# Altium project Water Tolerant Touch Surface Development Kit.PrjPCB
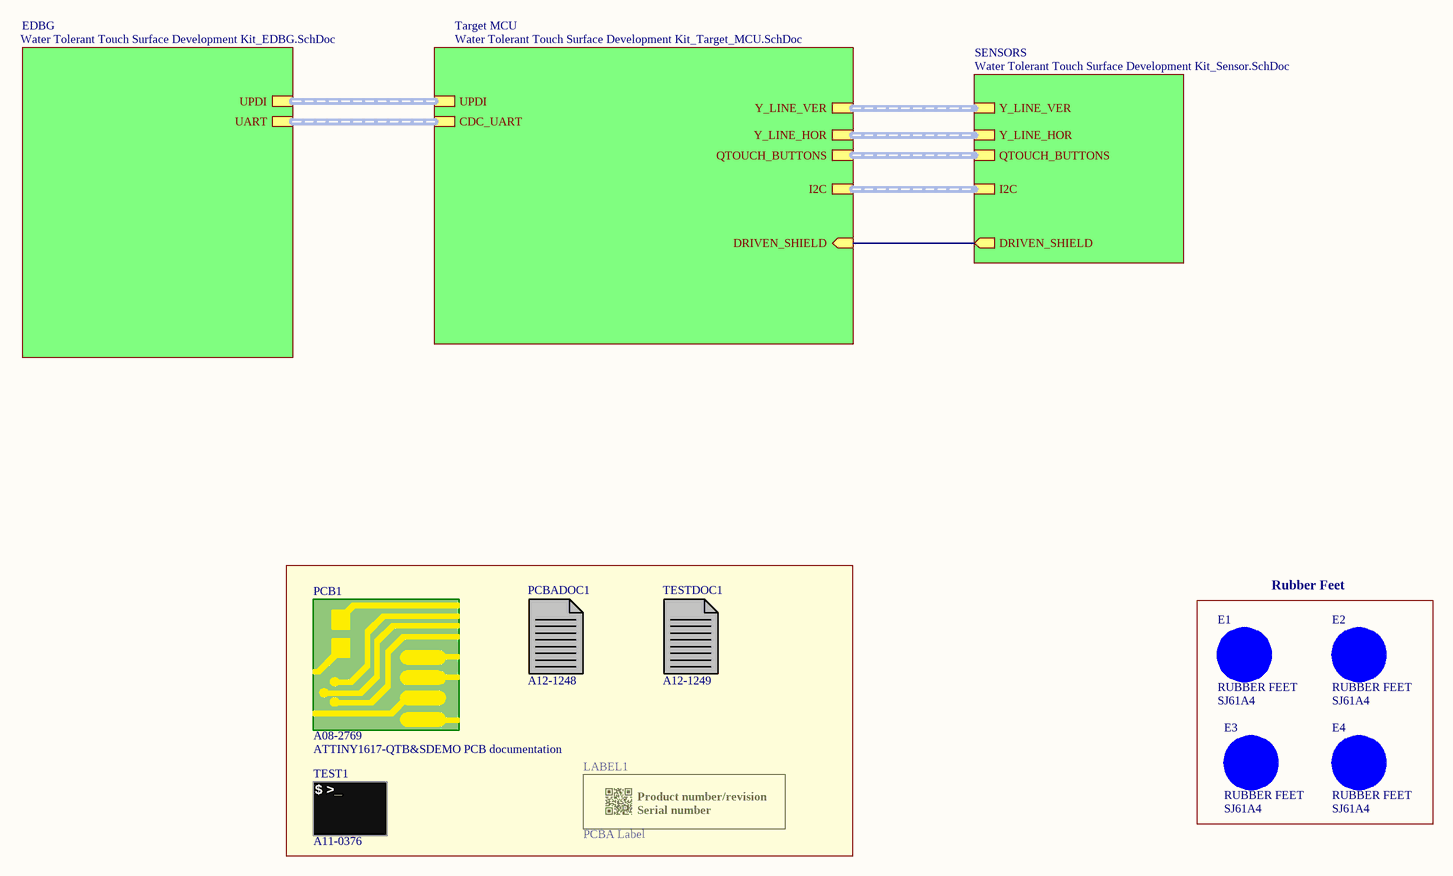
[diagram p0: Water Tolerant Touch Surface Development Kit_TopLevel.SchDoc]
4 sheets, 95 parts. Net scope: hierarchical (ports join the sheet entries above them; power ports are global).
Board file: Water Tolerant Touch Surface Development Kit.PcbDoc
Sheets:
  Water Tolerant Touch Surface Development Kit_TopLevel.SchDoc
    EDBG = Water Tolerant Touch Surface Development Kit_EDBG.SchDoc
    SENSORS = Water Tolerant Touch Surface Development Kit_Sensor.SchDoc
    Target MCU = Water Tolerant Touch Surface Development Kit_Target_MCU.SchDoc

## Sheet Water Tolerant Touch Surface Development Kit_TopLevel.SchDoc: Water Tolerant Touch Surface Development Kit
size A3; Author: Nitinkumar; CompanyName: Microchip; Engineer: Sivaram.SL; Organization: Microchip India; Address1: Sholinganallur; Address2: Chennai; Address3: INDIA; DocumentNumber: A09-3028; Revision: 3; SheetNumber: 1; SheetTotal: 4; PageSetup: Record=PageOptions¦CenterHorizontal=True¦CenterVertical=True¦PrintScale=1.01¦XCorrection=1.00¦YCorrection=1.00¦PrintKind=1¦BorderSize=5000000¦LeftOffset=0¦BottomOffset=0¦Orientation=2¦PaperLength=1000¦PaperWidth=1000¦Scale=100¦PaperSource=7¦PrintQuality=-4¦MediaType=1¦DitherType=10¦PaperKind=A3 (297 x 420 mm)¦PrintScaleMode=1; PCBNumber: A08-2769; PCBRevision: 3

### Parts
E1  RUBBER FEET  value SJ61A4  [AP8-01069]
E2  RUBBER FEET  value SJ61A4  [AP8-01069]
E3  RUBBER FEET  value SJ61A4  [AP8-01069]
E4  RUBBER FEET  value SJ61A4  [AP8-01069]
LABEL1  value PCBA Label  [AP8-00317]  (hidden comment: PCBA_LABEL)
PCB1  value ATTINY1617-QTB&SDEMO PCB documentation  AN: A08-2769  (hidden comment: PCB)  (mechanical)
PCBADOC1  AN: A12-1248  (hidden comment: PCBADOC)  (mechanical)
TEST1  AN: A11-0376  (hidden comment: TEST)  (mechanical)
TESTDOC1  AN: A12-1249  (hidden comment: TESTDOC)  (mechanical)

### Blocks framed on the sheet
Rubber Feet: E1-E4

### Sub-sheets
EDBG = Water Tolerant Touch Surface Development Kit_EDBG.SchDoc: UPDI (harness UPDI), UART (harness UART)
SENSORS = Water Tolerant Touch Surface Development Kit_Sensor.SchDoc: Y_LINE_VER (harness Y_LINE_VER), Y_LINE_HOR (harness Y_LINE_HOR), I2C (harness I2C), DRIVEN_SHIELD (out), QTOUCH_BUTTONS (harness QTOUCH_BUTTONS)
Target MCU = Water Tolerant Touch Surface Development Kit_Target_MCU.SchDoc: UPDI (harness UPDI), CDC_UART (harness CDC_UART), Y_LINE_VER (harness Y_LINE_HOR), Y_LINE_HOR (harness X LINES), I2C (harness I2C), DRIVEN_SHIELD (in), QTOUCH_BUTTONS (harness QTOUCH_BUTTONS)

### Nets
DRIVEN_SHIELD: sheet SENSORS/DRIVEN_SHIELD, sheet Target MCU/DRIVEN_SHIELD

Not connected (* = marked no-connect by the designer): E1 1(FIDUCIAL); E2 1(FIDUCIAL); E3 1(FIDUCIAL); E4 1(FIDUCIAL)

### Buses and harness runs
harness sheet EDBG/UART = sheet Target MCU/CDC_UART
harness sheet EDBG/UPDI = sheet Target MCU/UPDI
harness sheet SENSORS/I2C = sheet Target MCU/I2C
harness sheet SENSORS/QTOUCH_BUTTONS = sheet Target MCU/QTOUCH_BUTTONS
harness sheet SENSORS/Y_LINE_HOR = sheet Target MCU/Y_LINE_HOR
harness sheet SENSORS/Y_LINE_VER = sheet Target MCU/Y_LINE_VER

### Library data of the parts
E1-E4 = A08-2771: 7.9mm adhesive feet diam 9.5mm
LABEL1 = A09-0611: PCBA identification label PP Top White Gloss; PartGroup: Mechanical devices,Packaging materials,Printed Labels; Manufacturer: ACT Logimark AS; MPN: 505462; ComponentStatus: 'Active (verified)'
PCB1 = A08-2769: ATTINY1617-QTB&SDEMO PCB documentation
PCBADOC1 = A12-1248: ATTINY1617-QTB&SDEMO PCBA documentation
TEST1 = A11-0376: ATTINY1617-QTB&SDEMO Test Software
TESTDOC1 = A12-1249: ATTINY1617-QTB&SDEMO Test Instructions

## Sheet Water Tolerant Touch Surface Development Kit_EDBG.SchDoc: Water Tolerant Touch Surface Development Kit
size A3; Organization: Microchip India; Address1: Sholinganallur; Address2: Chennai; Address3: India; DocumentNumber: A09-3028; Revision: 3; SheetNumber: 3; SheetTotal: 4; PageSetup: Record=PageOptions¦CenterHorizontal=True¦CenterVertical=True¦PrintScale=1.01¦XCorrection=1.00¦YCorrection=1.00¦PrintKind=1¦BorderSize=5000000¦LeftOffset=0¦BottomOffset=0¦Orientation=2¦PaperLength=1000¦PaperWidth=1000¦Scale=100¦PaperSource=7¦PrintQuality=-4¦MediaType=1¦DitherType=10¦PaperKind=A3 (297 x 420 mm)¦PrintScaleMode=1; PCBNumber: A09-2769; PCBRevision: 3
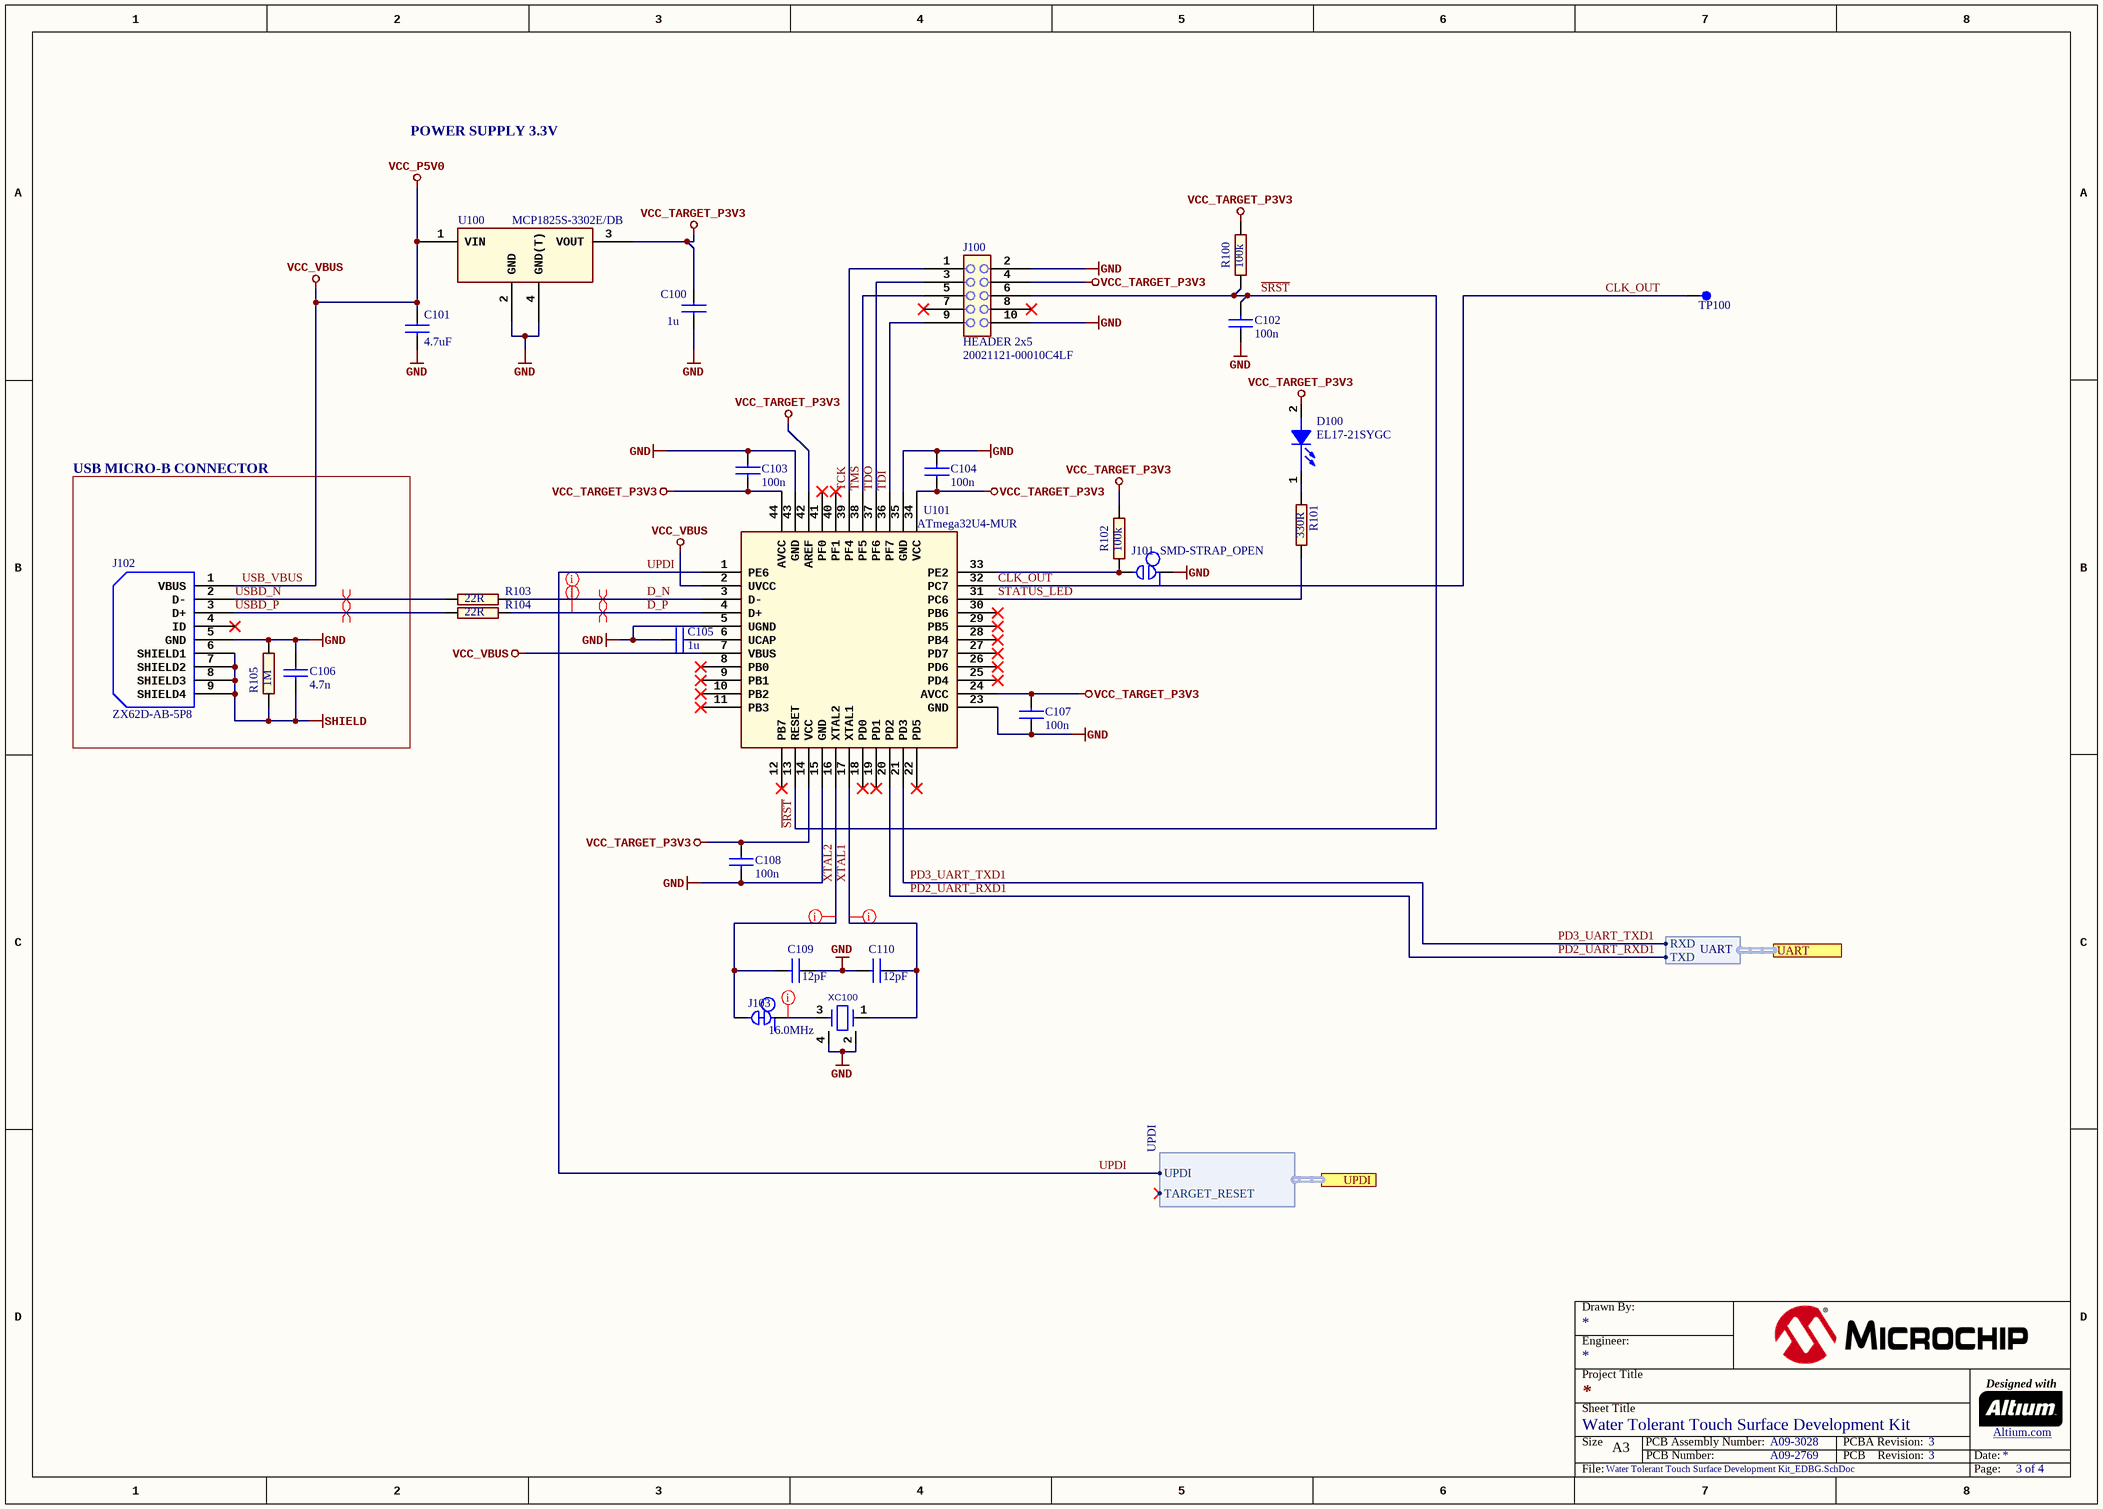
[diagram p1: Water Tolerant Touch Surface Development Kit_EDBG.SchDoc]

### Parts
C100  value 1u  [AP1-00001]
C101  value 4.7uF  [AP1-00039]  (hidden comment: CAP-NONPOL)
C102  value 100n  [AP1-00001]
C103  value 100n  [AP1-00001]
C104  value 100n  [AP1-00001]
C105  value 1u  [AP1-00001]
C106  value 4.7n  [AP1-00001]
C107  value 100n  [AP1-00001]
C108  value 100n  [AP1-00001]
C109  value 12pF  [AP1-00038]
C110  value 12pF  [AP1-00038]
D100  value EL17-21SYGC  [AP4-00013]
J100  HEADER 2x5  value 20021121-00010C4LF  [AP8-00109]
J101  value SMD-STRAP_OPEN  [AP9-00034]  (no BOM)
J102  value ZX62D-AB-5P8  [AP8-00852]  (hidden comment: 2,000 pieces per reel)
J103  (no value)  [AP9-00044]  (net tie, no BOM)
R100  value 100k  [AP2-00000]
R101  value 330R  [AP2-00000]  (hidden comment: R2)
R102  value 100k  [AP2-00000]
R103  value 22R  [AP2-00000]
R104  value 22R  [AP2-00000]
R105  value 1M  [AP2-00000]
TP100  (no value)  [AP8-00010]  (no BOM)
U100  value MCP1825S-3302E/DB  (hidden comment: MCP1825S-3302E_DB)
U101  value ATmega32U4-MUR  [AP6-00375]
XC100  value 16.0MHz  [AP7-00061]

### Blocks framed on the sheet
USB MICRO-B CONNECTOR: C106 J102 R105

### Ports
UART (harness UART), UPDI (harness UPDI)

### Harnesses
UART: RXD, TXD
UPDI: UPDI, TARGET_RESET

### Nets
GND: C100.2 C101.2 C102.1 C103.1 C104.2 C105.1 C106.1 C107.1 C108.2 C109.1 C110.2 J100.2 J100.10 J101.1 J102.5(GND) R105.2 U100.2(GND) U100.4(GND(T)) U101.5(UGND) U101.15(GND) U101.23(GND) U101.35(GND) U101.43(GND) U101.45(GND) XC100.2(GND) XC100.4(GND)
SHIELD: C106.2 J102.6(SHIELD1) J102.7(SHIELD2) J102.8(SHIELD3) J102.9(SHIELD4) R105.1
USB_VBUS: C101.1 J102.1(VBUS) U100.1(VIN) U101.2(UVCC) U101.7(VBUS)  [also labelled VCC_P5V0, VCC_VBUS]
VCC_TARGET_P3V3: C100.1 C103.2 C104.1 C107.2 C108.1 D100.2(ANODE) J100.4 R100.2 R102.2 U100.3(VOUT) U101.14(VCC) U101.24(AVCC) U101.34(VCC) U101.42(AREF) U101.44(AVCC)
CLK_OUT: TP100.1 U101.32(PC7)
D_N: R103.2 U101.3(D-)
D_P: R104.2 U101.4(D+)
PD2_UART_RXD1: U101.20(PD2) ; port UART.TXD  [project net PB2_UART_TX]
PD3_UART_TXD1: U101.21(PD3) ; port UART.RXD  [project net PB3_UART_RX]
~{SRST}: C102.2 J100.6 R100.1 U101.13(RESET)
STATUS_LED: R101.1 U101.31(PC6)
TCK: J100.1 U101.39(PF4)
TDI: J100.9 U101.36(PF7)
TDO: J100.3 U101.37(PF6)
TMS: J100.5 U101.38(PF5)
UPDI: U101.1(PE6) ; port UPDI.UPDI  [project net PA0_UPDI_RST]
USBD_N: J102.2(D-) R103.1
USBD_P: J102.3(D+) R104.1
XTAL1: C110.1 U101.17(XTAL1) XC100.1(IN)
XTAL2: C109.2 J103.2 U101.16(XTAL2)
NetC105_2: C105.2 U101.6(UCAP)
NetD100_1: D100.1(CATHODE) R101.2
NetJ101_2: J101.2 R102.1 U101.33(PE2)
NetJ103_1: J103.1 XC100.3(OUT)

Not connected (* = marked no-connect by the designer): J100 7* 8*; J102 4(ID)*; U101 8(PB0)* 9(PB1)* 10(PB2)* 11(PB3)* 12(PB7)* 18(PD0)* 19(PD1)* 22(PD5)* 25(PD4)* 26(PD6)* 27(PD7)* 28(PB4)* 29(PB5)* 30(PB6)* 40(PF1)* 41(PF0)*

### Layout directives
differential pair: D_N, D_P, USBD_N, USBD_P
rule Assembly Testpoint Usage [Testpoint - Not Allowed    Multiple - Not Allowed]: D_N, D_P, NetJ103_1, XTAL1, XTAL2

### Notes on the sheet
- POWER SUPPLY 3.3V

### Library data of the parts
C100 C105 = A01-0286: Ceramic capacitor, SMD 0402, X5R, 6.3V, +/-10% (de26942); PartGroup: Capacitors,Ceramic,SMD 0402; Manufacturer: Kemet; MPN: C0402C105K9PAC; TemperatureRange: -55 to 85 deg C; ComponentStatus: 'Active (verified)'
C101 = A01-0377: Ceramic capacitor, SMD 0603, X5R, 10V, 10% (de31036); PartGroup: Capacitors,Ceramic,SMD 0603; Manufacturer: WALSIN Technology Corporation; MPN: 0603X475K100CT; TemperatureRange: -55 - +85 deg C; ComponentStatus: 'Active (verified)'
C102-C104 C107 C108 = A01-0246: Ceramic capacitor, SMD 0402, X7R, 16V, +/-10%; PartGroup: Capacitors,Ceramic,SMD 0402; Manufacturer: Kemet; MPN: C0402C104K4RACTU; TemperatureRange: -55 - +125 deg C; ComponentStatus: 'Active (verified)'
C106 = A01-0046: Ceramic capacitor, SMD 0402, X7R, 25V, +/-10% (de35287); PartGroup: Capacitors,Ceramic,SMD 0402; TemperatureRange: -55 - +125 deg C; ComponentStatus: 'Active (verified)'
C109 C110 = A01-0355: Ceramic capacitor, SMD 0402, NP0, 50V, +/-5% (de19819); PartGroup: Capacitors,Ceramic,SMD 0402; Manufacturer: Kyocera-elco; MPN: CM05CG120J50AH; Tolerance: 5%; TemperatureRange: -55 - +125 deg C; ComponentStatus: 'Active (verified)'
D100 = A10-0018: LED, Green, Wave length=575nm, SMD 0805, ±70°; PartGroup: Opto,LEDs,SMD; Manufacturer: Everlight; TemperatureRange: -40 - +85 deg C; ComponentStatus: 'Active (verified)'
J100 = A08-0022: 2x5 pin header, 1.27mm pitch, SMD; PartGroup: Mechanical devices,Connectors,Pin headers; Manufacturer: HARWIN; MPN: M50-3600542; ComponentStatus: 'Active (verified)'
J101 = A09-0483: Default open SMD strap; PartGroup: Mechanical devices,PCB implemented components; ComponentStatus: 'Active (verified)'
J102 = A08-2112: Micro USB AB Connector, Standard SMT + DIP; PartGroup: Mechanical devices,Connectors,USB; Manufacturer: HIROSE; MPN: ZX62D-AB-5P8(30); ComponentStatus: 'Active (verified)'
J103 = A09-0783: Default closed SMD strap, 0603 size; PartGroup: Mechanical devices,PCB implemented components; Value: SMD-STRAP_0603_CLOSED; ComponentStatus: 'Active (verified)'
R100 R102 = A02-0260: Thick film resistor, SMD 0402, 1/16W, 1%; PartGroup: Resistors,SMD,0402 1%; Manufacturer: ASJ; MPN: CR10-1003-FK; TemperatureRange: -55ï¿½ to +125ï¿½C; ComponentStatus: 'Active (verified)'
R101 = A02-0200: Thick film resistor, SMD 0402, 1/16W, 1%; PartGroup: Resistors,SMD,0402 1%; TemperatureRange: -55 - +125 deg C; ComponentStatus: 'Active (verified)'
R103 R104 = A02-0172: Thick film resistor, SMD 0402, 1/16W, 1% (de23607); PartGroup: Resistors,SMD,0402 1%; Manufacturer: Samsung; MPN: RC100SF22R0CS; TemperatureRange: -55 - +125 deg C; ComponentStatus: 'Active (verified)'
R105 = A02-0284: Thick film resistor, SMD 0402, 1/16W, 1%; PartGroup: Resistors,SMD,0402 1%; Manufacturer: ASJ; MPN: CR10-1004-FK; TemperatureRange: -55 - +125 deg C; ComponentStatus: 'Active (verified)'
TP100 = A08-0004: Single SMD testpad; PartGroup: Mechanical devices,Connectors,Test points; ComponentStatus: 'Active (verified)'
U100 = A06-1533: LDO regulator, 3.3V fixed, 500mA, SOT-223
U101 = A06-0305: ATmega32U4 QFN package; PartGroup: Integrated Circuits,MCU, MPU, DSP,AVR MCU; Manufacturer: ATMEL; ComponentStatus: 'Active (verified)'
XC100 = A07-0078: 16MHz uXtal, 3.2 x 2.5 mm SMD, CL=9pF, 15PPM, ESR=80ohm(Max.; PartGroup: Frequency devices,Crystals,SMD; Manufacturer: Epson Toyocom; MPN: TSX-3225 16.0000MF09Z-AC3; TemperatureRange: -40Â°C to +85Â°C; ComponentStatus: 'Active (verified)'

## Sheet Water Tolerant Touch Surface Development Kit_Sensor.SchDoc: Water Tolerant Touch Surface Development Kit
size A3; Author: Nitinkumar; Organization: Microchip India; Address1: Sholinganallur; Address2: Chennai; Address3: India; DocumentNumber: A09-3028; Revision: 2; SheetNumber: 2; SheetTotal: 4; PageSetup: Record=PageOptions¦CenterHorizontal=True¦CenterVertical=True¦PrintScale=1.01¦XCorrection=1.00¦YCorrection=1.00¦PrintKind=1¦BorderSize=5000000¦LeftOffset=0¦BottomOffset=0¦Orientation=2¦PaperLength=1000¦PaperWidth=1000¦Scale=100¦PaperSource=7¦PrintQuality=-4¦MediaType=1¦DitherType=10¦PaperKind=A3 (297 x 420 mm)¦PrintScaleMode=1; PCBNumber: A09-2769; PCBRevision: 2
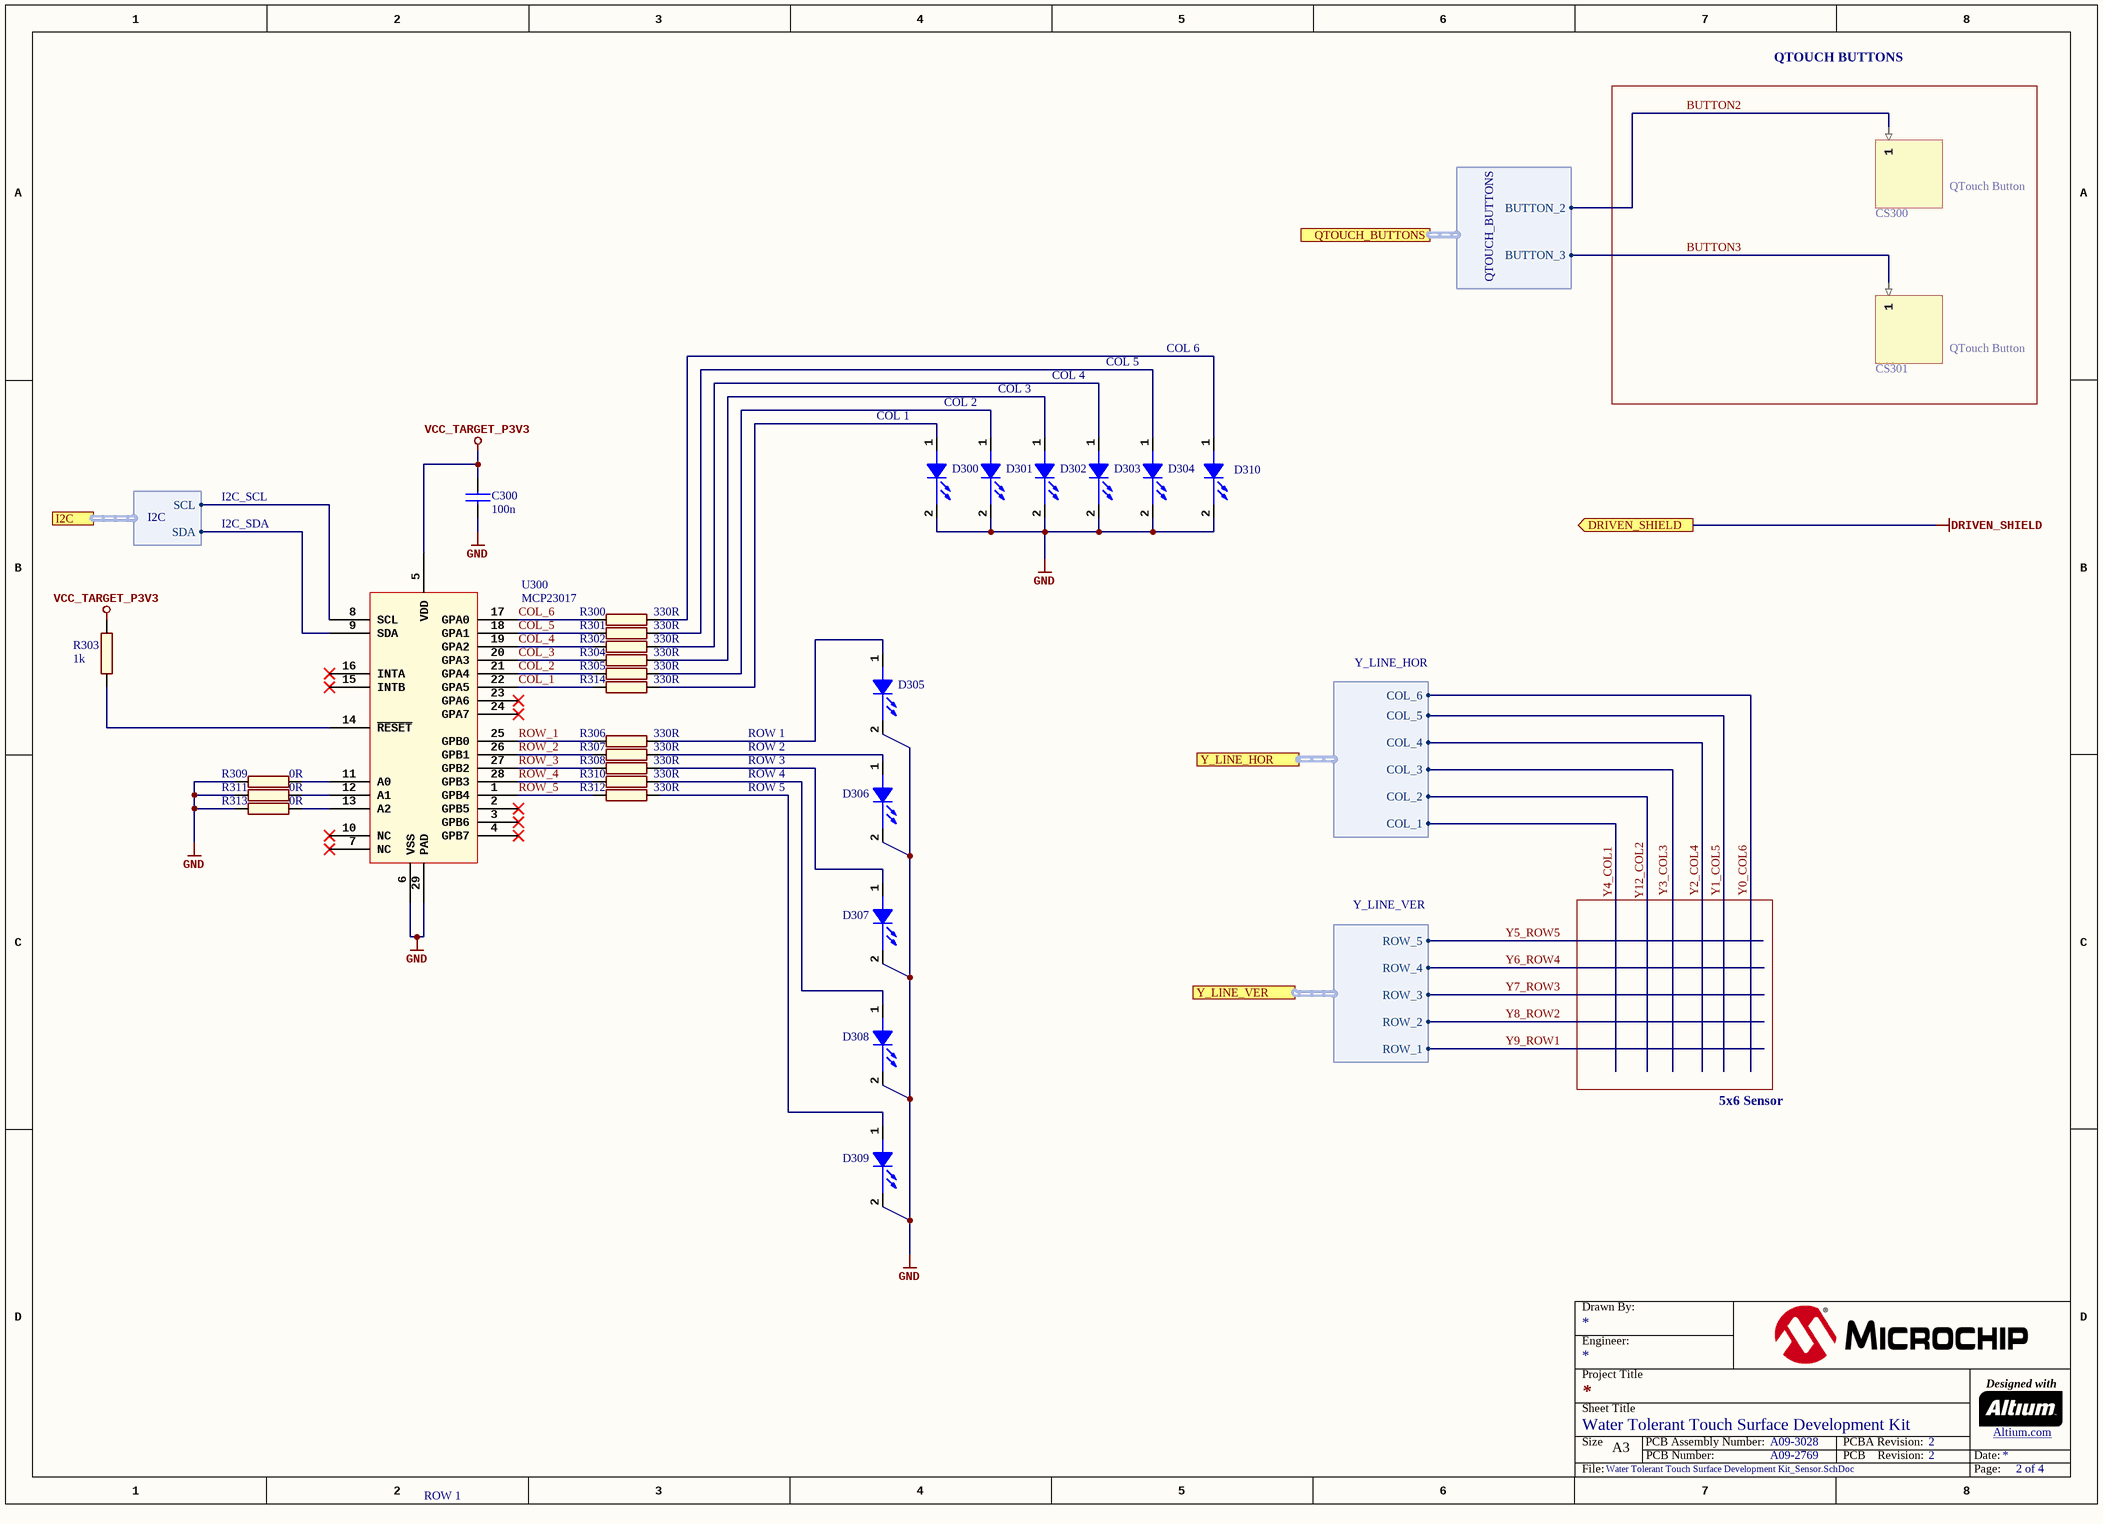
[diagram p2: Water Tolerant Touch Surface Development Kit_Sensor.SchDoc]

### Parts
C300  value 100n  [AP1-00053]
CS300  QTouch Button  (graphical)
CS301  QTouch Button  (graphical)
D300  LED_21  [AP4-00115]  (value not drawn)
D301  LED_21  [AP4-00115]  (value not drawn)
D302  LED_21  [AP4-00115]  (value not drawn)
D303  LED_21  [AP4-00115]  (value not drawn)
D304  LED_21  [AP4-00115]  (value not drawn)
D305  LED_21  [AP4-00115]  (value not drawn)
D306  LED_21  [AP4-00115]  (value not drawn)
D307  LED_21  [AP4-00115]  (value not drawn)
D308  LED_21  [AP4-00115]  (value not drawn)
D309  LED_21  [AP4-00115]  (value not drawn)
D310  LED_21  [AP4-00115]  (value not drawn)
R300  value 330R  [AP2-00000]  (hidden comment: R2)
R301  value 330R  [AP2-00000]  (hidden comment: R2)
R302  value 330R  [AP2-00000]  (hidden comment: R2)
R303  value 1k  [AP2-00011]
R304  value 330R  [AP2-00000]  (hidden comment: R2)
R305  value 330R  [AP2-00000]  (hidden comment: R2)
R306  value 330R  [AP2-00000]  (hidden comment: R2)
R307  value 330R  [AP2-00000]  (hidden comment: R2)
R308  value 330R  [AP2-00000]  (hidden comment: R2)
R309  value 0R  [AP2-00000]  (hidden comment: R2)
R310  value 330R  [AP2-00000]  (hidden comment: R2)
R311  value 0R  [AP2-00000]  (hidden comment: R2)
R312  value 330R  [AP2-00000]  (hidden comment: R2)
R313  value 0R  [AP2-00000]  (hidden comment: R2)
R314  value 330R  [AP2-00000]  (hidden comment: R2)
U300  value MCP23017  [AP6-00497]  (hidden comment: MCP23017-E_ML)

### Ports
DRIVEN_SHIELD (out), I2C (harness I2C), QTOUCH_BUTTONS (harness QTOUCH_BUTTONS), Y_LINE_HOR (harness Y_LINE_HOR), Y_LINE_VER (harness Y_LINE_VER)

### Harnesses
QTOUCH_BUTTONS: BUTTON_2, BUTTON_3
I2C: SDA, SCL
Y_LINE_VER: ROW_1, ROW_2, ROW_3, ROW_4, ROW_5
Y_LINE_HOR: COL_1, COL_2, COL_3, COL_4, COL_5, COL_6

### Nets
GND: C300.2 D300.2(CATHODE) D301.2(CATHODE) D302.2(CATHODE) D303.2(CATHODE) D304.2(CATHODE) D305.2(CATHODE) D306.2(CATHODE) D307.2(CATHODE) D308.2(CATHODE) D309.2(CATHODE) D310.2(CATHODE) R309.1 R311.1 R313.1 U300.6(VSS) U300.29(PAD)
VCC_TARGET_P3V3: C300.1 R303.2 U300.5(VDD)
BUTTON2: CS300.1 ; port QTOUCH_BUTTONS.BUTTON_2
BUTTON3: CS301.1 ; port QTOUCH_BUTTONS.BUTTON_3
COL_1: R314.1 U300.22(GPA5)
COL_2: R305.1 U300.21(GPA4)
COL_3: R304.1 U300.20(GPA3)
COL_4: R302.1 U300.19(GPA2)
COL_5: R301.1 U300.18(GPA1)
COL_6: R300.1 U300.17(GPA0)
PA1_I2C_SDA: U300.9(SDA) ; port I2C.SDA
PA2_I2C_SCL: U300.8(SCL) ; port I2C.SCL
ROW_1: R306.1 U300.25(GPB0)
ROW_2: R307.1 U300.26(GPB1)
ROW_3: R308.1 U300.27(GPB2)
ROW_4: R310.1 U300.28(GPB3)
ROW_5: R312.1 U300.1(GPB4)
NetD300_1: D300.1(ANODE) R314.2
NetD301_1: D301.1(ANODE) R305.2
NetD302_1: D302.1(ANODE) R304.2
NetD303_1: D303.1(ANODE) R302.2
NetD304_1: D304.1(ANODE) R301.2
NetD305_1: D305.1(ANODE) R306.2
NetD306_1: D306.1(ANODE) R307.2
NetD307_1: D307.1(ANODE) R308.2
NetD308_1: D308.1(ANODE) R310.2
NetD309_1: D309.1(ANODE) R312.2
NetD310_1: D310.1(ANODE) R300.2
NetR303_1: R303.1 U300.14(~{RESET})
NetR309_2: R309.2 U300.11(A0)
NetR311_2: R311.2 U300.12(A1)
NetR313_2: R313.2 U300.13(A2)

Not connected (* = marked no-connect by the designer): U300 2(GPB5)* 3(GPB6)* 4(GPB7)* 7(NC)* 10(NC)* 15(INTB)* 16(INTA)* 23(GPA6)* 24(GPA7)*

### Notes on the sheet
- QTOUCH BUTTONS
- COL 4
- COL 5
- COL 6
- (near D300) COL 1
- COL 2
- COL 3
- I2C_SCL
- I2C_SDA
- ROW 4
- ROW 3
- ROW 2
- ROW 1
- ROW 5
- 5x6 Sensor
- Labels drawn without touching a wire or pin: Y3_COL3

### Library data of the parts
C300 = A01-0246: as C102 on sheet Water Tolerant Touch Surface Development Kit_EDBG
CS300 CS301 = QTouchButton: ConfiguratorName: ATMEL_TOUCH; ConfigurationParameters: {}__sensorid[1]{}width[8]{}height[8]{}
D300-D310 = A10-0204: LED, SMD, RED, 3.2x1.2mm, reverse mount; Value: LTST-C250KRKT
R300-R302 R304-R308 R310 R312 R314 = A02-0200: Thick film resistor, SMD 0402, 1/16W, 1%; PartGroup: Resistors,SMD,0402 1%; Manufacturer: ASJ; MPN: CR10-3300-FK; TemperatureRange: -55 - +125 deg C; ComponentStatus: 'Active (verified)'
R303 = A02-0212: Thick film resistor, SMD 0402, 1/16W, 1%; PartGroup: Resistors,SMD,0402 1%; TemperatureRange: -55 - +125 deg C; ComponentStatus: 'Active (verified)'
R309 R311 R313 = A02-0163: RES 0.0 OHM 1/16W 0402 SMD; PartGroup: Resistors,SMD,0402 1%; Manufacturer: (n/a); MPN: RMCF0402ZT0R00; Tolerance: 1 %; TemperatureRange: -55 - +125 deg C; ComponentStatus: 'Active (verified)'
U300 = A06-1534: 16-Bit I/O Expander with I2C interface, 28-Lead QFN; PartGroup: Integrated Circuits,General linear; Manufacturer: Microchip Technology Inc; MPN: MCP23017-E/ML; TemperatureRange: -40Â°C to +125Â°C; ComponentStatus: 'Active (verified)'

## Sheet Water Tolerant Touch Surface Development Kit_Target_MCU.SchDoc: Water Tolerant Touch Surface Development Kit
size A3; Author: Nitinkumar; Engineer: Sivaram.SL; Organization: Microchip India; Address1: Sholinganallur; Address2: Chennai; Address3: India; DocumentNumber: A09-3028; Revision: 3; SheetNumber: 4; SheetTotal: 4; PageSetup: Record=PageOptions¦CenterHorizontal=True¦CenterVertical=True¦PrintScale=0.70¦XCorrection=1.00¦YCorrection=1.00¦PrintKind=1¦BorderSize=5000000¦LeftOffset=0¦BottomOffset=0¦Orientation=2¦PaperLength=1000¦PaperWidth=1000¦Scale=100¦PaperSource=7¦PrintQuality=-4¦MediaType=1¦DitherType=10¦PaperKind=A3 (297 x 420 mm)¦PrintScaleMode=1; PCBNumber: A09-2769; PCBRevision: 3
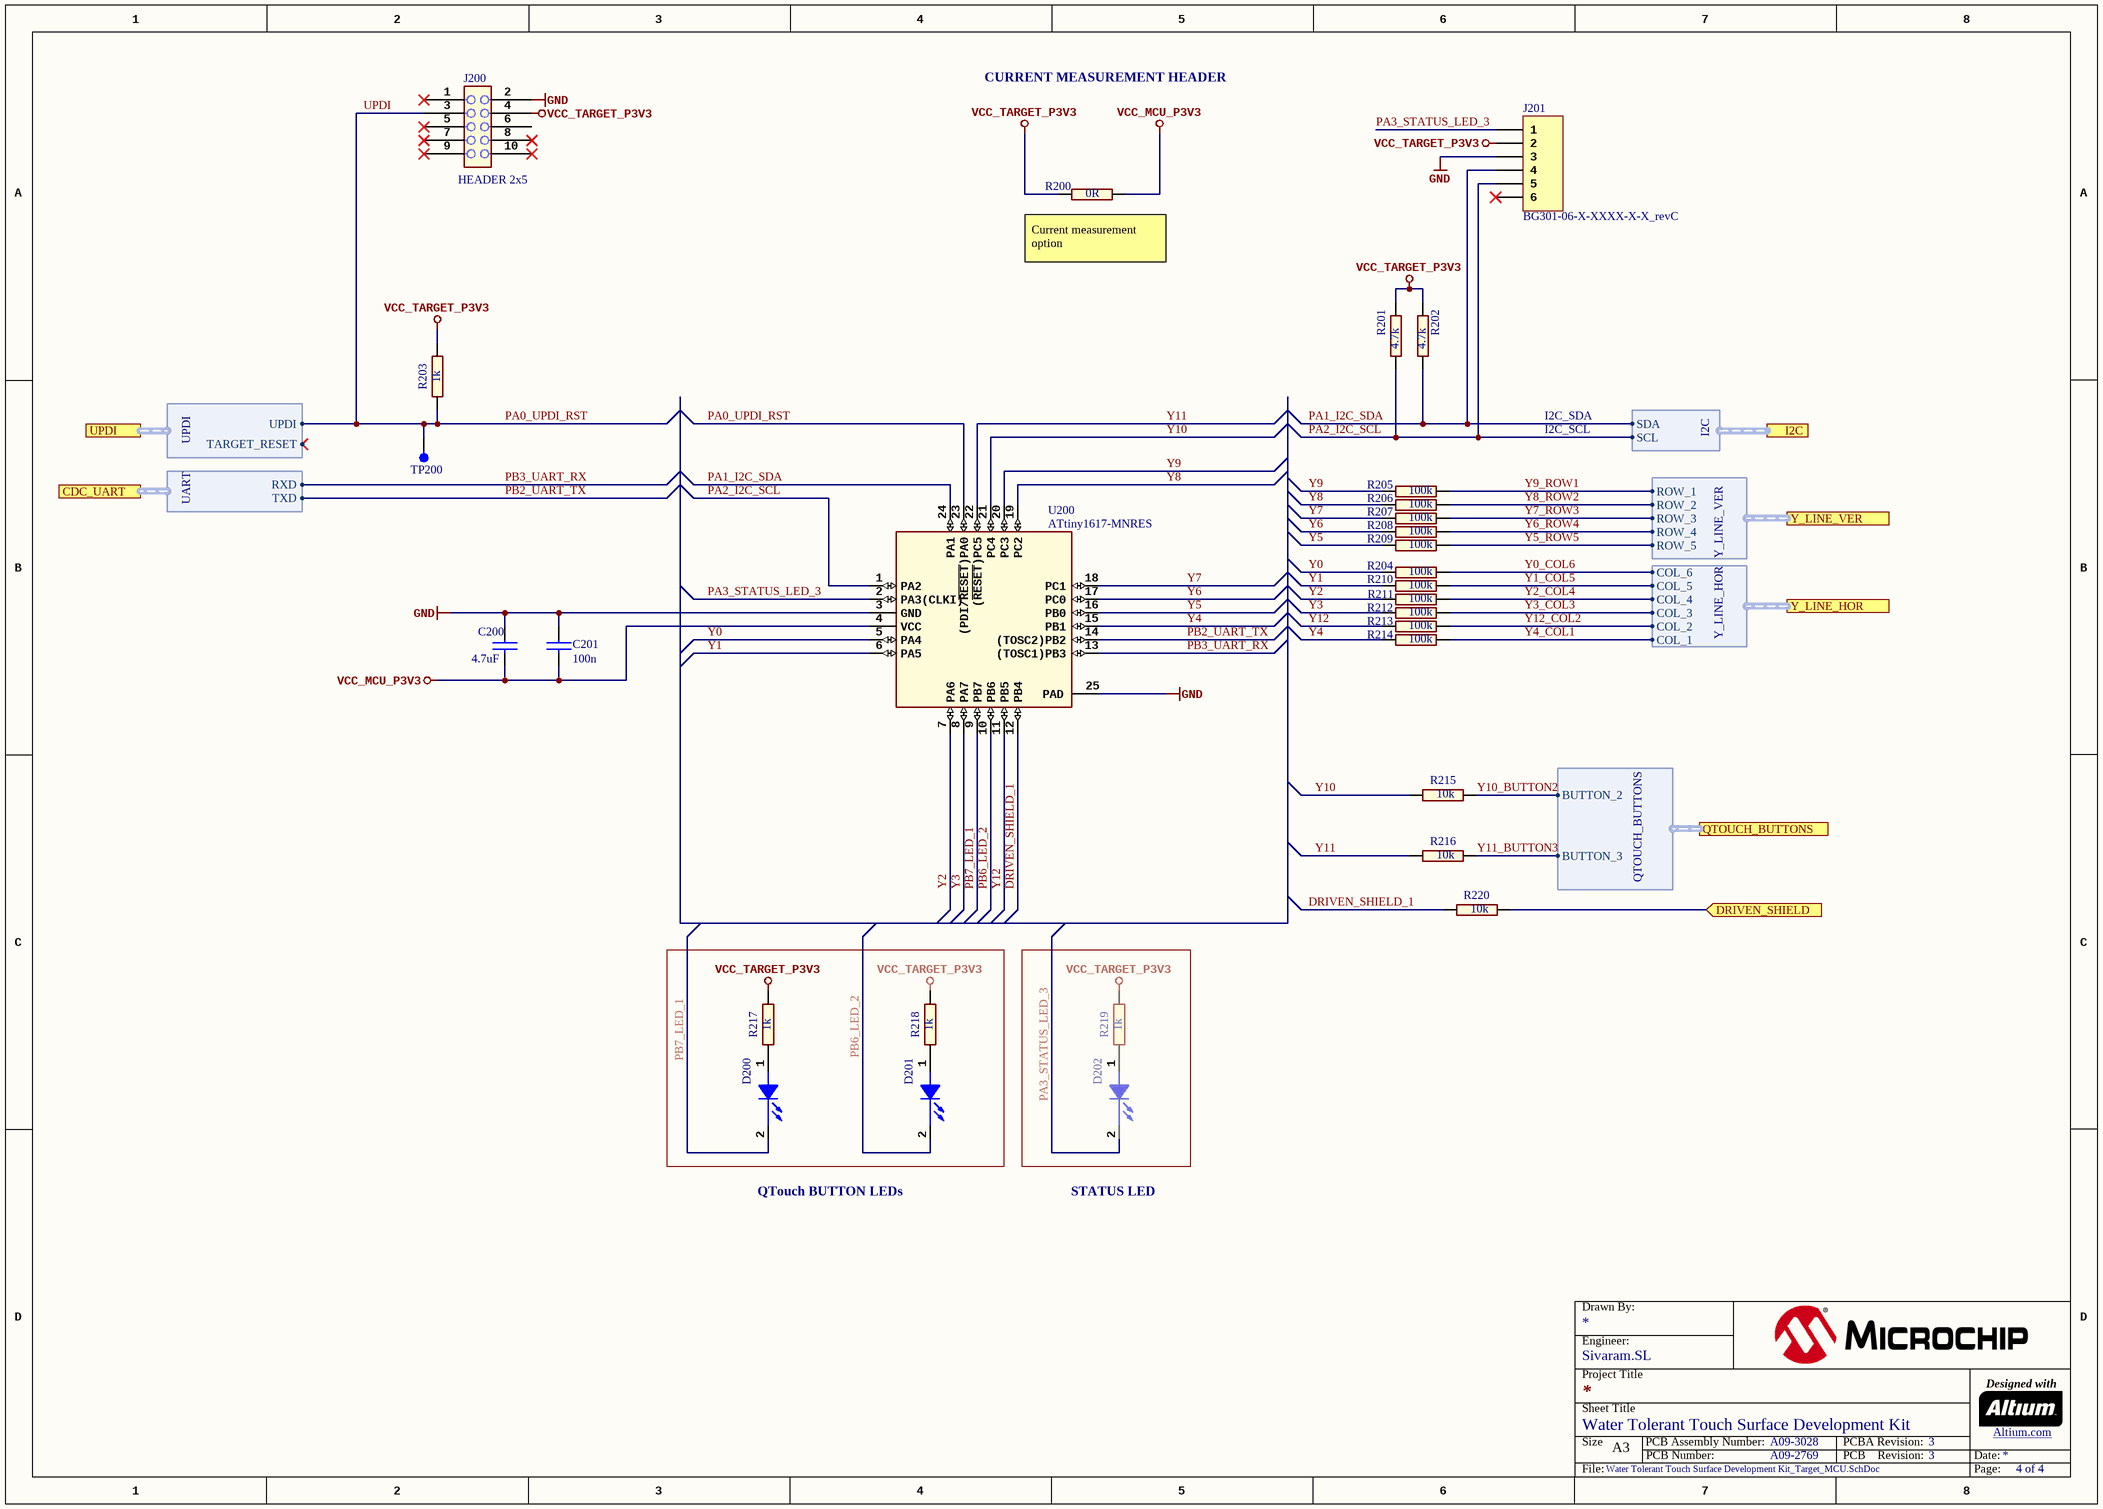
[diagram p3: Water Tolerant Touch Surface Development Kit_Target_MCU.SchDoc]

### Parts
C200  value 4.7uF  [AP1-00039]  (hidden comment: CAP-NONPOL)
C201  value 100n  [AP1-00053]
D200  LED_21  [AP4-00115]  (value not drawn)
D201  LED_21  [AP4-00115]  (value not drawn)
D202  LED_21  [AP4-00115]  (value not drawn)
J200  HEADER 2x5  [AP8-00109]
J201  BG301-06-X-XXXX-X-X_revC  [BG301-06-X-XXXX-X-X_revC]
R200  value 0R  [AP2-00000]
R201  value 4.7k  [AP2-00000]  (hidden comment: R2)
R202  value 4.7k  [AP2-00000]  (hidden comment: R2)
R203  value 1k  [AP2-00011]
R204  value 100k  [AP2-00001]  (hidden comment: R2)
R205  value 100k  [AP2-00001]  (hidden comment: R2)
R206  value 100k  [AP2-00001]  (hidden comment: R2)
R207  value 100k  [AP2-00001]  (hidden comment: R2)
R208  value 100k  [AP2-00001]  (hidden comment: R2)
R209  value 100k  [AP2-00001]  (hidden comment: R2)
R210  value 100k  [AP2-00001]  (hidden comment: R2)
R211  value 100k  [AP2-00001]  (hidden comment: R2)
R212  value 100k  [AP2-00001]  (hidden comment: R2)
R213  value 100k  [AP2-00001]  (hidden comment: R2)
R214  value 100k  [AP2-00001]  (hidden comment: R2)
R215  value 10k  [AP2-00001]  (hidden comment: R2)
R216  value 10k  [AP2-00001]  (hidden comment: R2)
R217  value 1k  [AP2-00011]
R218  value 1k  [AP2-00011]
R219  value 1k  [AP2-00011]
R220  value 10k  [AP2-00001]  (hidden comment: R2)
TP200  (no value)  [AP8-00010]  (no BOM)
U200  value ATtiny1617-MNRES  [AP6-00459]  (hidden comment: ATtiny807)

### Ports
CDC_UART (harness UART), DRIVEN_SHIELD (in), I2C (harness I2C), QTOUCH_BUTTONS (harness QTOUCH_BUTTONS), UPDI (harness UPDI), Y_LINE_HOR (harness Y_LINE_HOR), Y_LINE_VER (harness Y_LINE_VER)

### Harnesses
UPDI: UPDI, TARGET_RESET
UART: RXD, TXD
I2C: SDA, SCL
QTOUCH_BUTTONS: BUTTON_2, BUTTON_3
Y_LINE_VER: ROW_5, ROW_4, ROW_3, ROW_2, ROW_1
Y_LINE_HOR: COL_1, COL_2, COL_3, COL_4, COL_5, COL_6

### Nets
DRIVEN_SHIELD: R220.2 ; port DRIVEN_SHIELD
GND: C200.1 C201.1 J200.2 J201.3 U200.3(GND) U200.25(PAD)
VCC_MCU_P3V3: C200.2 C201.2 R200.2 U200.4(VCC)
VCC_TARGET_P3V3: J200.4 J201.2 R200.1 R201.2 R202.2 R203.2 R217.2 R218.2 R219.2
DRIVEN_SHIELD_1: R220.1 U200.12(PB4)
PA0_UPDI_RST: J200.3 R203.1 TP200.1 U200.23((PDI/~{RESET})PA0) ; port UPDI.UPDI  [also labelled UPDI]
PA1_I2C_SDA: J201.4 R202.1 U200.24(PA1) ; port I2C.SDA
PA2_I2C_SCL: J201.5 R201.1 U200.1(PA2) ; port I2C.SCL
PA3_STATUS_LED_3: D202.2(CATHODE) J201.1 U200.2(PA3(CLKI))
PB2_UART_TX: U200.14((TOSC2)PB2) ; port CDC_UART.TXD
PB3_UART_RX: U200.13((TOSC1)PB3) ; port CDC_UART.RXD
PB6_LED_2: D201.2(CATHODE) U200.10(PB6)
PB7_LED_1: D200.2(CATHODE) U200.9(PB7)
Y0: R204.1 U200.5(PA4)
Y0_COL6: R204.2 ; port Y_LINE_HOR.COL_6
Y1: R210.1 U200.6(PA5)
Y1_COL5: R210.2 ; port Y_LINE_HOR.COL_5
Y2: R211.1 U200.7(PA6)
Y2_COL4: R211.2 ; port Y_LINE_HOR.COL_4
Y3: R212.1 U200.8(PA7)
Y3_COL3: R212.2 ; port Y_LINE_HOR.COL_3
Y4: R214.1 U200.15(PB1)
Y4_COL1: R214.2 ; port Y_LINE_HOR.COL_1
Y5: R209.1 U200.16(PB0)
Y5_ROW5: R209.2 ; port Y_LINE_VER.ROW_5
Y6: R208.1 U200.17(PC0)
Y6_ROW4: R208.2 ; port Y_LINE_VER.ROW_4
Y7: R207.1 U200.18(PC1)
Y7_ROW3: R207.2 ; port Y_LINE_VER.ROW_3
Y8: R206.1 U200.19(PC2)
Y8_ROW2: R206.2 ; port Y_LINE_VER.ROW_2
Y9: R205.1 U200.20(PC3)
Y9_ROW1: R205.2 ; port Y_LINE_VER.ROW_1
Y10: R215.1 U200.21(PC4)
Y10_BUTTON2: R215.2 ; port QTOUCH_BUTTONS.BUTTON_2  [project net BUTTON2]
Y11: R216.1 U200.22((~{RESET})PC5)
Y11_BUTTON3: R216.2 ; port QTOUCH_BUTTONS.BUTTON_3  [project net BUTTON3]
Y12: R213.1 U200.11(PB5)
Y12_COL2: R213.2 ; port Y_LINE_HOR.COL_2
NetD200_1: D200.1(ANODE) R217.1
NetD201_1: D201.1(ANODE) R218.1
NetD202_1: D202.1(ANODE) R219.1

Not connected (* = marked no-connect by the designer): J200 1* 5* 6 7* 8* 9* 10*; J201 6*

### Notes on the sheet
- CURRENT MEASUREMENT HEADER
- (near R200) Current measurement option
- I2C_SDA
- I2C_SCL
- QTouch BUTTON LEDs
- STATUS LED

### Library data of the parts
C200 = A01-0377: as C101 on sheet Water Tolerant Touch Surface Development Kit_EDBG
C201 = A01-0246: as C102 on sheet Water Tolerant Touch Surface Development Kit_EDBG
D200-D202 = A10-0204: as D300 on sheet Water Tolerant Touch Surface Development Kit_Sensor
J200 = A08-0022: 2x5 pin header, 1.27mm pitch, SMD; PartGroup: Mechanical devices,Connectors,Pin headers; Manufacturer: HARWIN; MPN: M50-3600542; Value: 20021121-00010C4LF; ComponentStatus: 'Active (verified)'
J201 = BG301-06-X-XXXX-X-X_revC: 2.54mm Pitch Pin Header,Single Row, Surface Mount, Horizontal, Natural LCP
R200 = A02-0163: as R309 on sheet Water Tolerant Touch Surface Development Kit_Sensor
R201 R202 = A02-0228: Thick film resistor, SMD 0402, 1/16W, 1%; PartGroup: Resistors,SMD,0402 1%; Manufacturer: PHYCOMP; MPN: 2322 706 74702L; TemperatureRange: -55ï¿½ to +125ï¿½C; ComponentStatus: 'Active (verified)'
R203 R217-R219 = A02-0212: as R303 on sheet Water Tolerant Touch Surface Development Kit_Sensor
R204-R214 = A02-0122: Thick film resistor, SMD 0603, 1/10W, 1%; PartGroup: Resistors,SMD,0603 1%; Manufacturer: Panasonic; MPN: ERJ-3EKF1003V; ComponentStatus: 'Active (verified)'
R215 R216 R220 = A02-0098: Thick film resistor, SMD 0603, 1/10W, 1%; PartGroup: Resistors,SMD,0603 1%; Manufacturer: KOA; MPN: RK73H1JTTD1002F; ComponentStatus: 'Active (verified)'
TP200 = A08-0004: as TP100 on sheet Water Tolerant Touch Surface Development Kit_EDBG
U200 = A06-1500: Atmel 8-bit RISC MCU, QFN; PartGroup: Integrated Circuits,MCU, MPU, DSP,AVR MCU; TemperatureRange: -40Â°C +125Â°C; ComponentStatus: 'Active (verified)'

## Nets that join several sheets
GND: Water Tolerant Touch Surface Development Kit_EDBG (26 pins), Water Tolerant Touch Surface Development Kit_Sensor (17 pins), Water Tolerant Touch Surface Development Kit_Target_MCU (6 pins)
VCC_TARGET_P3V3: Water Tolerant Touch Surface Development Kit_EDBG (15 pins), Water Tolerant Touch Surface Development Kit_Sensor (C300.1 R303.2 U300.5), Water Tolerant Touch Surface Development Kit_Target_MCU (9 pins)
BUTTON2: Water Tolerant Touch Surface Development Kit_Sensor (CS300.1), Water Tolerant Touch Surface Development Kit_Target_MCU (R215.2)
BUTTON3: Water Tolerant Touch Surface Development Kit_Sensor (CS301.1), Water Tolerant Touch Surface Development Kit_Target_MCU (R216.2)
PA0_UPDI_RST: Water Tolerant Touch Surface Development Kit_EDBG (U101.1), Water Tolerant Touch Surface Development Kit_Target_MCU (J200.3 R203.1 TP200.1 U200.23)
PA1_I2C_SDA: Water Tolerant Touch Surface Development Kit_Sensor (U300.9), Water Tolerant Touch Surface Development Kit_Target_MCU (J201.4 R202.1 U200.24)
PA2_I2C_SCL: Water Tolerant Touch Surface Development Kit_Sensor (U300.8), Water Tolerant Touch Surface Development Kit_Target_MCU (J201.5 R201.1 U200.1)
PB2_UART_TX: Water Tolerant Touch Surface Development Kit_EDBG (U101.20), Water Tolerant Touch Surface Development Kit_Target_MCU (U200.14)
PB3_UART_RX: Water Tolerant Touch Surface Development Kit_EDBG (U101.21), Water Tolerant Touch Surface Development Kit_Target_MCU (U200.13)

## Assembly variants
Default: not fitted C106 J100 J201 R105 R203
